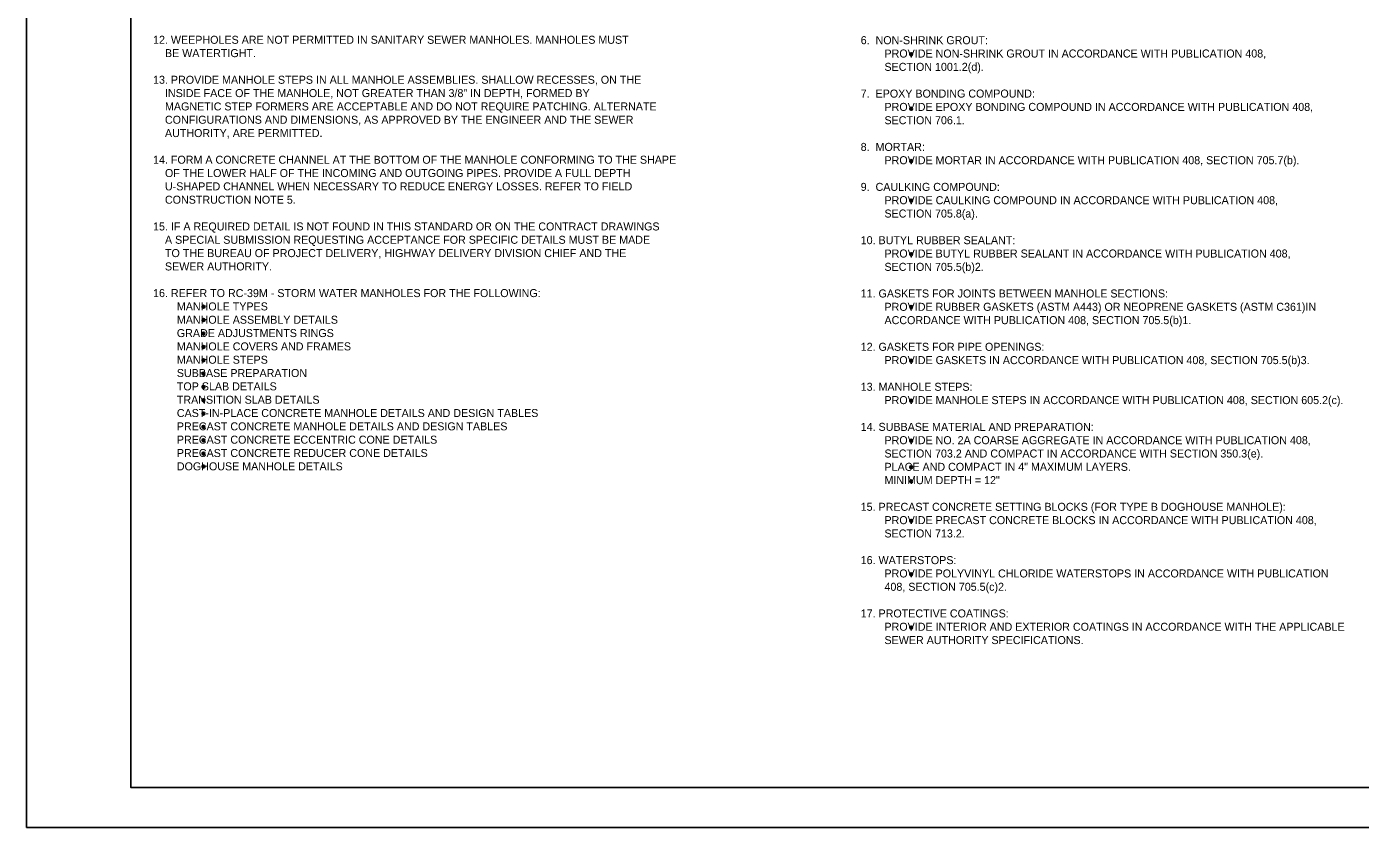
# Model space of a CAD drawing. Extents: x 2106427 to 2114911, y 988717 to 990787.
# Drawn here: x 2106427 to 2108067, y 988839 to 989824 of the extents above; entities that cross this region are included whole.
import ezdxf

# ---------------------------------------------------------------- set-up
doc = ezdxf.new("R2010")
doc.units = 0
for name, color, linetype in [('1', 7, 'Continuous'), ('3', 7, 'Continuous'), ('PLT-BNDY', 7, 'Continuous')]:
    doc.layers.add(name, color=color, linetype=linetype)

msp = doc.modelspace()

# ---------------------------------------------------------------- linework, layer by layer
at = {"layer": '1'}
msp.add_lwpolyline([(2109133.2, 988887.7), (2109133.2, 990738.1), (2106554.5, 990738.1), (2106554.5, 988887.7), (2109133.2, 988887.7), (2109133.2, 988974.2), (2108477, 988974.2), (2108477, 989186.4), (2109133.2, 989186.4), (2109133.2, 989281.4), (2108477, 989281.4), (2108477, 988887.7), (2108735.6, 988887.7), (2108735.6, 988974.2), (2108735.6, 988887.7), (2108988.2, 988887.7), (2108988.2, 988974.2), (2108988.2, 988933.8), (2109133.2, 988933.8)], dxfattribs=at)
for centre, radius in [((2107514.6, 989789.9), 1.75), ((2107514.6, 989789.9), 1.31), ((2107514.6, 989789.9), 0.875), ((2107514.6, 989789.9), 0.437), ((2107514.6, 989722.8), 1.75), ((2107514.6, 989722.8), 1.31), ((2107514.6, 989722.8), 0.875), ((2107514.6, 989722.8), 0.437), ((2107514.6, 989658.4), 1.75), ((2107514.6, 989658.4), 1.31), ((2107514.6, 989658.4), 0.875), ((2107514.6, 989658.4), 0.437), ((2107514.6, 989609.7), 1.75), ((2107514.6, 989609.7), 1.31), ((2107514.6, 989609.7), 0.875), ((2107514.6, 989609.7), 0.437), ((2107514.6, 989543.9), 1.75), ((2107514.6, 989543.9), 1.31), ((2107514.6, 989543.9), 0.875), ((2107514.6, 989543.9), 0.437), ((2106644, 989479.1), 1.75), ((2106644, 989479.1), 1.31), ((2106644, 989479.1), 0.875), ((2106644, 989479.1), 0.437), ((2107514.6, 989478.8), 1.75), ((2107514.6, 989478.8), 1.31), ((2107514.6, 989478.8), 0.875), ((2107514.6, 989478.8), 0.437), ((2106644, 989462.8), 1.75), ((2106644, 989462.8), 1.31), ((2106644, 989462.8), 0.875), ((2106644, 989462.8), 0.437), ((2106644, 989446), 1.75), ((2106644, 989446), 1.31), ((2106644, 989446), 0.875), ((2106644, 989446), 0.437), ((2106644, 989429.6), 1.75), ((2106644, 989429.6), 1.31), ((2106644, 989429.6), 0.875), ((2106644, 989429.6), 0.437), ((2106644, 989413.2), 1.75), ((2106644, 989413.2), 1.31), ((2106644, 989413.2), 0.875), ((2106644, 989413.2), 0.437), ((2107514.6, 989412.7), 1.75), ((2107514.6, 989412.7), 1.31), ((2107514.6, 989412.7), 0.875), ((2107514.6, 989412.7), 0.437), ((2106644, 989396.8), 1.75), ((2106644, 989396.8), 1.31), ((2106644, 989396.8), 0.875), ((2106644, 989396.8), 0.437), ((2106644, 989380.4), 1.75), ((2106644, 989380.4), 1.31), ((2106644, 989380.4), 0.875), ((2106644, 989380.4), 0.437), ((2106644, 989364), 1.75), ((2106644, 989364), 1.31), ((2106644, 989364), 0.875), ((2106644, 989364), 0.437), ((2107514.6, 989363.5), 1.75), ((2107514.6, 989363.5), 1.31), ((2107514.6, 989363.5), 0.875), ((2107514.6, 989363.5), 0.437), ((2106644, 989347.6), 1.75), ((2106644, 989347.6), 1.31), ((2106644, 989347.6), 0.875), ((2106644, 989347.6), 0.437), ((2106644, 989331.2), 1.75), ((2106644, 989331.2), 1.31), ((2106644, 989331.2), 0.875), ((2106644, 989331.2), 0.437), ((2106644, 989314.8), 1.75), ((2106644, 989314.8), 1.31), ((2106644, 989314.8), 0.875), ((2106644, 989314.8), 0.437), ((2107514.6, 989314.3), 1.75), ((2107514.6, 989314.3), 1.31), ((2107514.6, 989314.3), 0.875), ((2107514.6, 989314.3), 0.437), ((2106644, 989298.4), 1.75), ((2106644, 989298.4), 1.31), ((2106644, 989298.4), 0.875), ((2106644, 989298.4), 0.437), ((2106644, 989282.5), 1.75), ((2106644, 989282.5), 1.31), ((2106644, 989282.5), 0.875), ((2106644, 989282.5), 0.437), ((2107514.6, 989281.7), 1.75), ((2107514.6, 989281.7), 1.31), ((2107514.6, 989281.7), 0.875), ((2107514.6, 989281.7), 0.437), ((2107514.6, 989264.2), 1.75), ((2107514.6, 989264.2), 1.31), ((2107514.6, 989264.2), 0.875), ((2107514.6, 989264.2), 0.437), ((2107514.6, 989215.7), 1.75), ((2107514.6, 989215.7), 1.31), ((2107514.6, 989215.7), 0.875), ((2107514.6, 989215.7), 0.437), ((2107514.6, 989149.9), 1.75), ((2107514.6, 989149.9), 1.31), ((2107514.6, 989149.9), 0.875), ((2107514.6, 989149.9), 0.437), ((2107514.6, 989084.5), 1.75), ((2107514.6, 989084.5), 1.31), ((2107514.6, 989084.5), 0.875), ((2107514.6, 989084.5), 0.437)]:
    msp.add_circle(centre, radius, dxfattribs=at)
at = {"layer": 'PLT-BNDY'}
msp.add_lwpolyline([(2106426.5, 990787.3), (2109185.7, 990787.3), (2109185.7, 988838.5), (2106426.5, 988838.5)], close=True, dxfattribs=at)

# ---------------------------------------------------------------- texts
at = {"layer": '3'}
for s, p in [('12. WEEPHOLES ARE NOT PERMITTED IN SANITARY SEWER MANHOLES. MANHOLES MUST', (2106582, 989802.7)), ('6.  NON-SHRINK GROUT:', (2107452.5, 989802.2)), ('    BE WATERTIGHT.', (2106582, 989786.3)), ('        PROVIDE NON-SHRINK GROUT IN ACCORDANCE WITH PUBLICATION 408,', (2107452.5, 989785.8)), ('        SECTION 1001.2(d).', (2107452.5, 989769.4)), ('13. PROVIDE MANHOLE STEPS IN ALL MANHOLE ASSEMBLIES. SHALLOW RECESSES, ON THE ', (2106582, 989753.5)), ('    INSIDE FACE OF THE MANHOLE, NOT GREATER THAN 3/8" IN DEPTH, FORMED BY ', (2106582, 989737.1)), ('7.  EPOXY BONDING COMPOUND:', (2107452.5, 989736.5)), ('    MAGNETIC STEP FORMERS ARE ACCEPTABLE AND DO NOT REQUIRE PATCHING. ALTERNATE', (2106582, 989720.7)), ('        PROVIDE EPOXY BONDING COMPOUND IN ACCORDANCE WITH PUBLICATION 408,', (2107452.5, 989720.1)), ('    CONFIGURATIONS AND DIMENSIONS, AS APPROVED BY THE ENGINEER AND THE SEWER', (2106582, 989704.3)), ('        SECTION 706.1.', (2107452.5, 989703.7)), ('    AUTHORITY, ARE PERMITTED.', (2106582, 989687.9)), ('8.  MORTAR:', (2107452.5, 989670.9)), ('14. FORM A CONCRETE CHANNEL AT THE BOTTOM OF THE MANHOLE CONFORMING TO THE SHAPE', (2106582, 989655.1)), ('        PROVIDE MORTAR IN ACCORDANCE WITH PUBLICATION 408, SECTION 705.7(b).', (2107452.5, 989654.5)), ('    OF THE LOWER HALF OF THE INCOMING AND OUTGOING PIPES. PROVIDE A FULL DEPTH', (2106582, 989638.7)), ('    U-SHAPED CHANNEL WHEN NECESSARY TO REDUCE ENERGY LOSSES. REFER TO FIELD', (2106582, 989622.3)), ('9.  CAULKING COMPOUND:', (2107452.5, 989621.7)), ('    CONSTRUCTION NOTE 5.', (2106582, 989605.9)), ('        PROVIDE CAULKING COMPOUND IN ACCORDANCE WITH PUBLICATION 408,', (2107452.5, 989605.3)), ('        SECTION 705.8(a).', (2107452.5, 989588.9)), ('15. IF A REQUIRED DETAIL IS NOT FOUND IN THIS STANDARD OR ON THE CONTRACT DRAWINGS', (2106582, 989573)), ('    A SPECIAL SUBMISSION REQUESTING ACCEPTANCE FOR SPECIFIC DETAILS MUST BE MADE', (2106582, 989556.6)), ('10. BUTYL RUBBER SEALANT:', (2107452.5, 989556.1)), ('    TO THE BUREAU OF PROJECT DELIVERY, HIGHWAY DELIVERY DIVISION CHIEF AND THE', (2106582, 989540.2)), ('        PROVIDE BUTYL RUBBER SEALANT IN ACCORDANCE WITH PUBLICATION 408, ', (2107452.5, 989539.7)), ('    SEWER AUTHORITY.', (2106582, 989523.8)), ('        SECTION 705.5(b)2.', (2107452.5, 989523.3)), ('16. REFER TO RC-39M - STORM WATER MANHOLES FOR THE FOLLOWING:', (2106582, 989491)), ('11. GASKETS FOR JOINTS BETWEEN MANHOLE SECTIONS:', (2107452.5, 989490.5)), ('        MANHOLE TYPES', (2106582, 989474.6)), ('        PROVIDE RUBBER GASKETS (ASTM A443) OR NEOPRENE GASKETS (ASTM C361)IN ', (2107452.5, 989474.1)), ('        MANHOLE ASSEMBLY DETAILS', (2106582, 989458.2)), ('        ACCORDANCE WITH PUBLICATION 408, SECTION 705.5(b)1.', (2107452.5, 989457.7)), ('        GRADE ADJUSTMENTS RINGS', (2106582, 989441.8)), ('        MANHOLE COVERS AND FRAMES', (2106582, 989425.4)), ('12. GASKETS FOR PIPE OPENINGS:', (2107452.5, 989424.9)), ('        MANHOLE STEPS', (2106582, 989409)), ('        PROVIDE GASKETS IN ACCORDANCE WITH PUBLICATION 408, SECTION 705.5(b)3.     ', (2107452.5, 989408.5)), ('        SUBBASE PREPARATION', (2106582, 989392.6)), ('        TOP SLAB DETAILS', (2106582, 989376.2)), ('13. MANHOLE STEPS:', (2107452.5, 989375.7)), ('        TRANSITION SLAB DETAILS', (2106582, 989359.8)), ('        PROVIDE MANHOLE STEPS IN ACCORDANCE WITH PUBLICATION 408, SECTION 605.2(c).', (2107452.5, 989359.3)), ('        CAST-IN-PLACE CONCRETE MANHOLE DETAILS AND DESIGN TABLES', (2106582, 989343.4)), ('        PRECAST CONCRETE MANHOLE DETAILS AND DESIGN TABLES', (2106582, 989327)), ('14. SUBBASE MATERIAL AND PREPARATION:', (2107452.5, 989326.4)), ('        PRECAST CONCRETE ECCENTRIC CONE DETAILS', (2106582, 989310.6)), ('        PROVIDE NO. 2A COARSE AGGREGATE IN ACCORDANCE WITH PUBLICATION 408,', (2107452.5, 989310)), ('        PRECAST CONCRETE REDUCER CONE DETAILS', (2106582, 989294.2)), ('        SECTION 703.2 AND COMPACT IN ACCORDANCE WITH SECTION 350.3(e).', (2107452.5, 989293.6)), ('        DOGHOUSE MANHOLE DETAILS', (2106582, 989277.8)), ('        PLACE AND COMPACT IN 4" MAXIMUM LAYERS.', (2107452.5, 989277.2)), ('        MINIMUM DEPTH = 12" ', (2107452.5, 989260.8)), ('15. PRECAST CONCRETE SETTING BLOCKS (FOR TYPE B DOGHOUSE MANHOLE):', (2107452.5, 989228)), ('        PROVIDE PRECAST CONCRETE BLOCKS IN ACCORDANCE WITH PUBLICATION 408,', (2107452.5, 989211.6)), ('        SECTION 713.2.', (2107452.5, 989195.2)), ('16. WATERSTOPS:', (2107452.5, 989162.4)), ('        PROVIDE POLYVINYL CHLORIDE WATERSTOPS IN ACCORDANCE WITH PUBLICATION', (2107452.5, 989146)), ('        408, SECTION 705.5(c)2.', (2107452.5, 989129.6)), ('17. PROTECTIVE COATINGS:', (2107452.5, 989096.8)), ('        PROVIDE INTERIOR AND EXTERIOR COATINGS IN ACCORDANCE WITH THE APPLICABLE', (2107452.5, 989080.4)), ('        SEWER AUTHORITY SPECIFICATIONS.', (2107452.5, 989064))]:
    msp.add_text(s, height=9.843, dxfattribs=at).set_placement(p)

doc.saveas('drawing.dxf')
